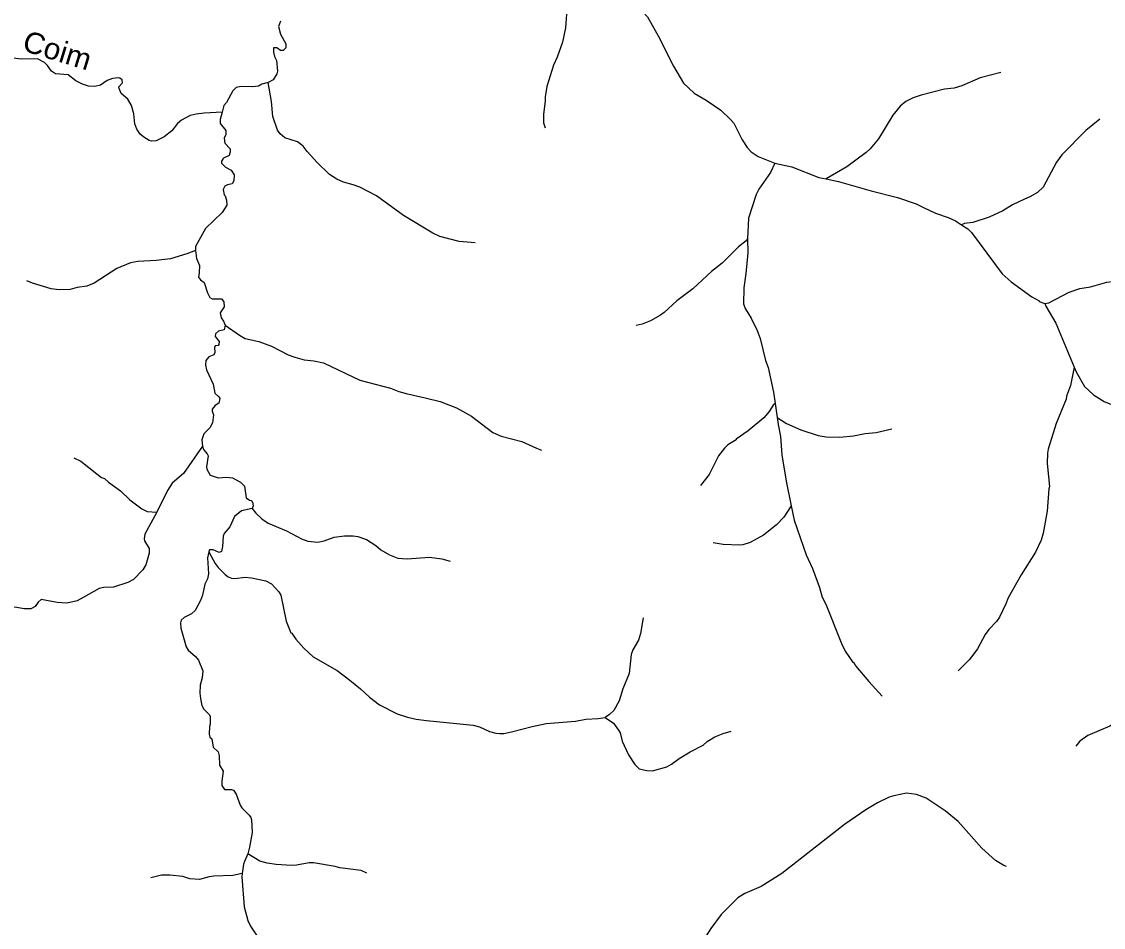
# Model space of a CAD drawing. Extents: x 551.6 to 577.6, y 7567 to 7594.7.
# Drawn here: x 558.55 to 563.65, y 7586.53 to 7590.81 of the extents above; entities that cross this region are included whole.
import ezdxf
from ezdxf.enums import TextEntityAlignment as Align

# ---------------------------------------------------------------- set-up
doc = ezdxf.new("R2010")
doc.units = 0
doc.header["$LTSCALE"] = 0.04
doc.layers.add('61', color=7, linetype='Continuous')
doc.layers.add('7', color=7, linetype='Continuous', lineweight=25)

msp = doc.modelspace()

# ---------------------------------------------------------------- linework, layer by layer
at = {"layer": '7'}
for points in [[(561.1096, 7590.9836), (561.1189, 7590.9434), (561.1245, 7590.8855), (561.1173, 7590.7793), (561.102, 7590.7117), (561.0771, 7590.6408), (561.0602, 7590.6022), (561.0296, 7590.5024), (561.0207, 7590.4541), (561.0215, 7590.4348), (561.0127, 7590.3704), (561.0135, 7590.3302), (561.0207, 7590.3068)], [(561.4806, 7590.8554), (561.5028, 7590.8308), (561.5543, 7590.7406), (561.6259, 7590.5974), (561.6726, 7590.5185), (561.7233, 7590.471), (561.7797, 7590.4372)], [(559.7725, 7590.8098), (559.7628, 7590.7857), (559.7725, 7590.7495), (559.7974, 7590.7028), (559.7974, 7590.6843), (559.7854, 7590.6714), (559.7805, 7590.6714)], [(559.7805, 7590.6714), (559.7725, 7590.6714), (559.7556, 7590.6851), (559.7403, 7590.6851), (559.7403, 7590.6634), (559.7451, 7590.644), (559.7548, 7590.6247), (559.7588, 7590.5748), (559.7564, 7590.5611), (559.7387, 7590.5338), (559.7144, 7590.5204)], [(558.8969, 7590.5024), (558.8679, 7590.504), (558.8389, 7590.5137), (558.8083, 7590.5281), (558.7713, 7590.5571), (558.7118, 7590.5611), (558.6932, 7590.5748), (558.6747, 7590.6006), (558.6595, 7590.6159), (558.6273, 7590.632), (558.554, 7590.6312), (558.4841, 7590.6393)], [(559.4973, 7590.3812), (559.4136, 7590.3768), (559.3749, 7590.372), (559.3468, 7590.3648), (559.3065, 7590.343), (559.288, 7590.3269), (559.2598, 7590.2931), (559.2252, 7590.265), (559.1866, 7590.2465), (559.1641, 7590.2448), (559.1544, 7590.2473), (559.1278, 7590.2626), (559.1117, 7590.2771), (559.0948, 7590.3012), (559.0868, 7590.3253), (559.082, 7590.3736), (559.0707, 7590.4123), (559.0538, 7590.442), (559.0216, 7590.4686), (559.0119, 7590.4927), (559.0111, 7590.5008), (559.0272, 7590.5193), (559.0256, 7590.533), (559.016, 7590.5418), (559.0095, 7590.5434), (558.9806, 7590.5402), (558.9564, 7590.5297), (558.9242, 7590.5088), (558.8969, 7590.5024)], [(559.7144, 7590.5204), (559.6856, 7590.5136), (559.6695, 7590.504), (559.6405, 7590.5), (559.5874, 7590.5024), (559.5632, 7590.4967), (559.5487, 7590.4815), (559.519, 7590.4267), (559.5053, 7590.4131), (559.4973, 7590.3812)], [(559.8803, 7590.2199), (559.853, 7590.2416), (559.7934, 7590.2601), (559.7709, 7590.2795), (559.7588, 7590.2964), (559.7371, 7590.3608), (559.7306, 7590.4316), (559.7144, 7590.5204)], [(563.1696, 7590.5684), (563.0722, 7590.5426), (562.9853, 7590.5048), (562.9498, 7590.4943), (562.9048, 7590.4895), (562.7937, 7590.4613), (562.7567, 7590.4485), (562.7213, 7590.4308), (562.6955, 7590.409), (562.6601, 7590.3664), (562.5925, 7590.2545), (562.5539, 7590.2086), (562.5346, 7590.1901), (562.4428, 7590.1233), (562.3461, 7590.0661)], [(561.7797, 7590.4372), (561.8489, 7590.3897), (561.8955, 7590.3471), (561.91, 7590.3286), (561.9503, 7590.2497), (561.9736, 7590.2135), (561.9929, 7590.1942), (562.0259, 7590.1716), (562.1047, 7590.1398)], [(559.4973, 7590.3812), (559.4884, 7590.3463), (559.4892, 7590.327), (559.5149, 7590.2948), (559.5149, 7590.2762), (559.5069, 7590.2585), (559.5101, 7590.2352), (559.5351, 7590.2086), (559.5359, 7590.1934), (559.531, 7590.1772), (559.5005, 7590.1619), (559.5004, 7590.1595)], [(563.6363, 7590.3487), (563.5711, 7590.2948), (563.4577, 7590.1789), (563.4327, 7590.1451), (563.3691, 7590.0276), (563.3426, 7590.0026), (563.3072, 7589.9809), (563.2814, 7589.9712), (563.2251, 7589.943), (563.1784, 7589.9149), (563.114, 7589.8859), (563.0384, 7589.8602), (562.9977, 7589.855), (562.9845, 7589.8499)], [(560.6908, 7589.7652), (560.6159, 7589.77), (560.5242, 7589.795), (560.492, 7589.8094), (560.3536, 7589.894), (560.2264, 7589.9857), (560.1475, 7590.0268), (560.1161, 7590.0388), (560.0703, 7590.0509), (560.0381, 7590.0646), (560.0035, 7590.0871), (559.9455, 7590.1435), (559.8988, 7590.195), (559.8803, 7590.2199)], [(559.5004, 7590.1595), (559.494, 7590.1499), (559.494, 7590.141), (559.5133, 7590.1217), (559.5407, 7590.1081), (559.5552, 7590.0855), (559.5536, 7590.0565), (559.5447, 7590.0428), (559.5238, 7590.0388), (559.5101, 7590.0316), (559.5021, 7590.0155), (559.5069, 7589.9913), (559.5117, 7589.9857), (559.5182, 7589.9664), (559.5198, 7589.9415), (559.498, 7589.9076), (559.42, 7589.832), (559.3725, 7589.7475), (559.3725, 7589.7288)], [(562.1047, 7590.1398), (562.0839, 7590.0968), (562.0283, 7590.0179), (562.0155, 7589.9922), (561.9792, 7589.8811), (561.9751, 7589.7827)], [(562.1047, 7590.1398), (562.1837, 7590.1225), (562.3108, 7590.0734), (562.3461, 7590.0661)], [(562.3461, 7590.0661), (562.4042, 7590.0541), (562.5587, 7590.0098), (562.6827, 7589.9785), (562.7712, 7589.9479), (562.8058, 7589.931)], [(562.8058, 7589.931), (562.8613, 7589.9052), (562.9209, 7589.8843), (562.9555, 7589.8682), (562.9845, 7589.8499)], [(562.9845, 7589.8499), (563.0142, 7589.8312), (563.0319, 7589.8135), (563.176, 7589.6179), (563.2178, 7589.5801), (563.316, 7589.5101), (563.3498, 7589.4907), (563.3504, 7589.4878), (563.3765, 7589.4781)], [(561.9751, 7589.7827), (561.9696, 7589.774), (561.9326, 7589.7459), (561.8561, 7589.6686), (561.8054, 7589.63), (561.7169, 7589.5479), (561.6412, 7589.4907), (561.5817, 7589.436), (561.5648, 7589.4232), (561.5173, 7589.3966), (561.4787, 7589.3813), (561.4505, 7589.3749)], [(561.9751, 7589.7827), (561.976, 7589.7169), (561.968, 7589.6203), (561.9583, 7589.5527), (561.9567, 7589.4771), (561.9639, 7589.4546), (561.9929, 7589.4095), (562.0211, 7589.3515), (562.0356, 7589.3129), (562.0605, 7589.2099), (562.0718, 7589.1761), (562.0984, 7589.0602), (562.1059, 7589.0057), (562.1148, 7588.9401), (562.1193, 7588.9073)], [(559.3725, 7589.7288), (559.3315, 7589.7121), (559.2542, 7589.6895), (559.1866, 7589.6815), (559.0997, 7589.6767), (559.0659, 7589.6694), (559.0015, 7589.6429), (558.8937, 7589.5744), (558.8599, 7589.5608), (558.8148, 7589.5543), (558.781, 7589.5447), (558.7295, 7589.5431), (558.6908, 7589.5471), (558.6039, 7589.5736), (558.5774, 7589.5849)], [(559.3725, 7589.7288), (559.3773, 7589.6912), (559.391, 7589.6574), (559.3902, 7589.6236), (559.3862, 7589.6026), (559.3959, 7589.5905), (559.4135, 7589.5769), (559.428, 7589.5286)], [(563.3765, 7589.4781), (563.3957, 7589.4819), (563.4923, 7589.5318), (563.5422, 7589.5487), (563.5921, 7589.5567), (563.6693, 7589.5785), (563.7757, 7589.5914)], [(559.428, 7589.5286), (559.4401, 7589.5068), (559.4506, 7589.5004), (559.494, 7589.5004), (559.5061, 7589.4867), (559.5069, 7589.4626), (559.4892, 7589.4336), (559.4932, 7589.4111), (559.5045, 7589.395), (559.5126, 7589.3753)], [(563.3765, 7589.4781), (563.3812, 7589.4658), (563.4295, 7589.3853), (563.5154, 7589.1773), (563.5245, 7589.1552)], [(559.5126, 7589.3753), (559.5069, 7589.3539), (559.4804, 7589.3475), (559.4666, 7589.3354), (559.465, 7589.3226), (559.4844, 7589.2992), (559.4828, 7589.2847), (559.4796, 7589.2807), (559.4642, 7589.2783), (559.461, 7589.2702), (559.4634, 7589.2469), (559.4594, 7589.2356), (559.4353, 7589.226), (559.4216, 7589.2091), (559.42, 7589.1874), (559.424, 7589.1648), (559.4554, 7589.098), (559.4634, 7589.0545), (559.482, 7589.0376)], [(559.5126, 7589.3753), (559.5793, 7589.3282), (559.6059, 7589.3137), (559.6711, 7589.2984), (559.7307, 7589.2775), (559.8095, 7589.2356), (559.8401, 7589.2244), (559.8852, 7589.2131), (559.9302, 7589.2083), (559.9753, 7589.1986), (560.1475, 7589.1165), (560.2924, 7589.0795), (560.331, 7589.0634), (560.3648, 7589.0537), (560.455, 7589.0328)], [(563.5154, 7589.1773), (563.4979, 7589.0908), (563.4794, 7589.0409), (563.4778, 7589.0264), (563.4303, 7588.9121), (563.3925, 7588.7914), (563.3893, 7588.7721), (563.3884, 7588.7238), (563.3989, 7588.6143), (563.3957, 7588.6031), (563.3876, 7588.4985), (563.3699, 7588.3954), (563.3603, 7588.3616), (563.3337, 7588.3053), (563.2661, 7588.1975)], [(563.5245, 7589.1552), (563.5647, 7589.0859), (563.6066, 7589.0473), (563.6565, 7589.0151), (563.7627, 7588.9741), (563.7772, 7588.9636), (563.7828, 7588.9628), (563.811, 7588.9282), (563.8174, 7588.9105), (563.8206, 7588.8671), (563.8367, 7588.8397), (563.8585, 7588.8195), (563.8939, 7588.8043), (563.9228, 7588.7737), (563.9333, 7588.7544), (563.9382, 7588.7363)], [(559.482, 7589.0376), (559.4876, 7589.0296), (559.4828, 7589.0087), (559.4642, 7588.9966), (559.4514, 7588.9797), (559.4506, 7588.9701), (559.457, 7588.9523), (559.4522, 7588.9153), (559.4393, 7588.8912), (559.4111, 7588.863), (559.4023, 7588.8349), (559.405, 7588.805)], [(560.455, 7589.0328), (560.5258, 7589.0151), (560.6031, 7588.9861), (560.6731, 7588.9467), (560.7737, 7588.8694), (560.8139, 7588.8517), (560.9113, 7588.8276), (560.9797, 7588.7954), (561.003, 7588.7866)], [(562.1059, 7589.0057), (562.0968, 7588.999), (562.0774, 7588.9692), (562.0517, 7588.9395), (561.9776, 7588.8767), (561.9221, 7588.8389), (561.9221, 7588.8356), (561.8819, 7588.8107), (561.8666, 7588.7954), (561.8384, 7588.76), (561.7941, 7588.6707), (561.7539, 7588.62)], [(562.1148, 7588.9401), (562.1587, 7588.9113), (562.2271, 7588.8815), (562.3076, 7588.8558), (562.3462, 7588.8485), (562.4106, 7588.8469), (562.475, 7588.8534), (562.5297, 7588.8654), (562.5813, 7588.8703), (562.6561, 7588.8864)], [(562.1193, 7588.9073), (562.1305, 7588.851), (562.1378, 7588.764), (562.1579, 7588.6401), (562.1813, 7588.5242)], [(559.405, 7588.805), (559.3154, 7588.6755), (559.2622, 7588.6304), (559.2405, 7588.5966), (559.1904, 7588.4939)], [(559.405, 7588.805), (559.4095, 7588.7898), (559.4272, 7588.7689), (559.4312, 7588.7592), (559.4248, 7588.7077), (559.4264, 7588.6964), (559.4409, 7588.6691), (559.4796, 7588.6554), (559.5182, 7588.6586), (559.5472, 7588.6554), (559.5842, 7588.636), (559.6035, 7588.6159), (559.6115, 7588.5612), (559.6276, 7588.5499), (559.6357, 7588.5483), (559.6373, 7588.5435)], [(558.7979, 7588.7495), (558.8309, 7588.7342), (558.9065, 7588.6739), (558.9291, 7588.6578), (558.9427, 7588.6522), (558.9612, 7588.6353), (559.0184, 7588.5942), (559.0619, 7588.5515), (559.119, 7588.5089), (559.1447, 7588.4968), (559.1904, 7588.4939)], [(559.6373, 7588.5435), (559.6415, 7588.5404), (559.6445, 7588.5233), (559.6392, 7588.5114)], [(559.1904, 7588.4939), (559.1335, 7588.3906), (559.1295, 7588.3681), (559.1311, 7588.3584), (559.1544, 7588.323), (559.1544, 7588.3005), (559.1383, 7588.2457), (559.1238, 7588.2216), (559.0804, 7588.1765), (559.053, 7588.1612), (558.9854, 7588.1395), (558.9403, 7588.1379), (558.9178, 7588.1331), (558.843, 7588.0912)], [(559.6392, 7588.5114), (559.589, 7588.5008), (559.556, 7588.4727), (559.5343, 7588.4244), (559.5077, 7588.3938), (559.5021, 7588.381), (559.4988, 7588.3311), (559.494, 7588.3085), (559.4844, 7588.3029), (559.4554, 7588.3165), (559.438, 7588.3163), (559.4356, 7588.307)], [(559.6392, 7588.5114), (559.6574, 7588.4888), (559.6848, 7588.4622), (559.7154, 7588.4413), (559.8015, 7588.4059), (559.8723, 7588.3672), (559.9013, 7588.3568), (559.9496, 7588.352), (559.9785, 7588.3584), (560.0268, 7588.3761), (560.0751, 7588.3825), (560.1153, 7588.3825), (560.1379, 7588.3793), (560.1781, 7588.3648), (560.2232, 7588.3367), (560.2465, 7588.3157), (560.2876, 7588.2924), (560.3262, 7588.2763), (560.3697, 7588.2739), (560.4759, 7588.2819), (560.5338, 7588.2739), (560.5733, 7588.2618)], [(562.1813, 7588.5242), (562.1466, 7588.4695), (562.112, 7588.4332), (562.0509, 7588.3849), (561.9873, 7588.3503), (561.9535, 7588.3399), (561.9374, 7588.3383), (561.8602, 7588.3415), (561.8127, 7588.3488)], [(562.1813, 7588.5242), (562.1949, 7588.4566), (562.2521, 7588.2924), (562.281, 7588.228), (562.314, 7588.1379), (562.3277, 7588.0928), (562.3446, 7588.059), (562.4187, 7587.8739), (562.4364, 7587.8385), (562.4702, 7587.787)], [(559.4356, 7588.307), (559.428, 7588.2779), (559.4329, 7588.2023), (559.4288, 7588.1798), (559.4168, 7588.154), (559.4047, 7588.1025), (559.395, 7588.0767), (559.3709, 7588.03), (559.354, 7588.0139), (559.3186, 7587.9962), (559.3049, 7587.9842), (559.3017, 7587.9721), (559.3025, 7587.9464), (559.3282, 7587.8578), (559.3379, 7587.8425), (559.3717, 7587.8128), (559.3862, 7587.795), (559.4063, 7587.7452), (559.4039, 7587.7114)], [(559.4356, 7588.307), (559.465, 7588.2514), (559.4787, 7588.232), (559.5117, 7588.199), (559.5262, 7588.1886), (559.5423, 7588.1822), (559.5584, 7588.1805), (559.6067, 7588.1878), (559.6357, 7588.1846), (559.7033, 7588.1701), (559.7306, 7588.1556), (559.7644, 7588.1186), (559.7741, 7588.1025), (559.7998, 7587.9802), (559.8224, 7587.9238), (559.8264, 7587.9222), (559.8449, 7587.894), (559.8836, 7587.8514), (559.9278, 7587.8119), (560.0397, 7587.746), (560.0992, 7587.7009)], [(563.2661, 7588.1975), (563.2041, 7588.0896), (563.1937, 7588.0606), (563.1639, 7587.9979), (563.1494, 7587.9785), (563.1132, 7587.9407), (563.0963, 7587.9158), (563.0593, 7587.8482), (563.0424, 7587.8256), (563.0198, 7587.7967), (562.9684, 7587.7444)], [(558.843, 7588.0912), (558.8148, 7588.0759), (558.7649, 7588.0638), (558.7198, 7588.0671), (558.645, 7588.0815), (558.6305, 7588.0687), (558.616, 7588.0494), (558.5959, 7588.0381), (558.5637, 7588.0381), (558.5202, 7588.0461), (558.4947, 7588.043)], [(561.4835, 7587.9954), (561.4706, 7587.9206), (561.461, 7587.89), (561.4344, 7587.845), (561.4263, 7587.8224), (561.4175, 7587.7323), (561.3869, 7587.6599), (561.3692, 7587.6035), (561.3443, 7587.5584), (561.325, 7587.5391), (561.3043, 7587.5256)], [(562.4702, 7587.787), (562.4774, 7587.7822), (562.4798, 7587.7757), (562.4831, 7587.7757), (562.4863, 7587.7677), (562.5466, 7587.6953), (562.6094, 7587.6252)], [(559.4039, 7587.7114), (559.3942, 7587.6776), (559.3926, 7587.6405), (559.3958, 7587.6148), (559.4023, 7587.5818), (559.4119, 7587.5649), (559.4385, 7587.5375), (559.4409, 7587.5295), (559.4409, 7587.4941), (559.4377, 7587.4828), (559.4361, 7587.4458), (559.4393, 7587.4329), (559.449, 7587.424), (559.4554, 7587.3846), (559.4795, 7587.3629), (559.4844, 7587.3444), (559.4852, 7587.3001), (559.5021, 7587.2711), (559.4956, 7587.2253), (559.4956, 7587.2035), (559.5093, 7587.185), (559.5423, 7587.1858), (559.5512, 7587.1826), (559.5632, 7587.1625), (559.5833, 7587.111), (559.5914, 7587.0981), (559.6252, 7587.0643), (559.6332, 7587.053), (559.6365, 7587.0418), (559.6389, 7586.9822), (559.6276, 7586.913), (559.6187, 7586.8813), (559.6035, 7586.8454)], [(560.0992, 7587.7009), (560.1499, 7587.6606), (560.1926, 7587.6204), (560.2401, 7587.5842), (560.323, 7587.5415), (560.3713, 7587.527), (560.4131, 7587.5166), (560.4614, 7587.5101), (560.6819, 7587.4884), (560.7109, 7587.4804), (560.7592, 7587.4586), (560.7882, 7587.4506), (560.8075, 7587.449), (560.8268, 7587.4498), (560.8622, 7587.457), (560.9596, 7587.482)], [(564.1276, 7587.6019), (564.0589, 7587.5729), (563.9816, 7587.5528), (563.943, 7587.552), (563.8593, 7587.56), (563.84, 7587.5584), (563.7788, 7587.5431), (563.7546, 7587.5319), (563.6838, 7587.4836), (563.5792, 7587.4401), (563.5422, 7587.4128), (563.5237, 7587.3902)], [(560.9596, 7587.482), (561.0264, 7587.4965), (561.1648, 7587.5069), (561.2131, 7587.5166), (561.271, 7587.5198), (561.3043, 7587.5256)], [(561.3043, 7587.5256), (561.3434, 7587.4981), (561.3676, 7587.4651), (561.374, 7587.4522), (561.3845, 7587.4136), (561.4135, 7587.3492), (561.444, 7587.3025), (561.4642, 7587.2832), (561.5012, 7587.2743), (561.527, 7587.2735), (561.5946, 7587.2928), (561.6171, 7587.3041), (561.6525, 7587.3323), (561.704, 7587.3637)], [(561.704, 7587.3637), (561.766, 7587.3943), (561.7845, 7587.4112), (561.8215, 7587.4337), (561.8602, 7587.4498), (561.898, 7587.4603)], [(563.1969, 7586.8212), (563.1832, 7586.8261), (563.1446, 7586.851), (563.0794, 7586.9082), (562.9692, 7587.0337), (562.908, 7587.0844), (562.8179, 7587.144), (562.7728, 7587.1609), (562.7245, 7587.1673), (562.665, 7587.156), (562.6424, 7587.1488), (562.5877, 7587.123), (562.5329, 7587.09), (562.4324, 7587.02), (562.1378, 7586.789)], [(559.6035, 7586.8454), (559.5986, 7586.8333), (559.5927, 7586.7884)], [(560.1805, 7586.7899), (560.154, 7586.8027), (560.0526, 7586.8156), (560.03, 7586.822), (559.9286, 7586.8389), (559.9077, 7586.8389), (559.8482, 7586.8277), (559.824, 7586.826), (559.7532, 7586.8309), (559.7097, 7586.8373), (559.6759, 7586.8478), (559.6187, 7586.8813)], [(559.5927, 7586.7884), (559.5488, 7586.7794), (559.4586, 7586.7762), (559.4361, 7586.7729), (559.391, 7586.7601), (559.346, 7586.7641), (559.3122, 7586.7754), (559.251, 7586.7818), (559.2124, 7586.7818), (559.1617, 7586.7681)], [(559.5927, 7586.7884), (559.5906, 7586.773), (559.6019, 7586.6313), (559.6188, 7586.5669), (559.6316, 7586.5412), (559.6598, 7586.4975)], [(562.1378, 7586.789), (562.0388, 7586.7271), (561.9632, 7586.6949), (561.9302, 7586.6739), (561.8505, 7586.5959), (561.8022, 7586.5291), (561.7104, 7586.3867), (561.6734, 7586.3392), (561.6195, 7586.2844), (561.5761, 7586.2522), (561.4835, 7586.2032), (561.4642, 7586.1694), (561.4585, 7586.1468), (561.4561, 7586.1066), (561.4352, 7586.0615), (561.3644, 7585.9585), (561.3104, 7585.8885), (561.2388, 7585.8184)]]:
    msp.add_lwpolyline(points, dxfattribs=at)

# ---------------------------------------------------------------- texts
at = {"layer": '61', "width": 1.05}
msp.add_text('Coim', height=0.1, rotation=342.869, dxfattribs=at).set_placement((558.7063, 7590.6252), align=Align.CENTER)

doc.saveas('drawing.dxf')
